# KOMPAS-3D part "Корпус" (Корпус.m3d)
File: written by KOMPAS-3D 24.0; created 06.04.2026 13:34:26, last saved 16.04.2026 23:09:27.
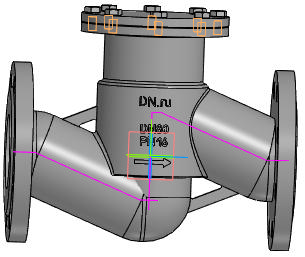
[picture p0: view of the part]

Document properties: Автор: R2D2; Полное имя файла: E:\Работа\Зайцев\VSO3131M-F-S Клапан запорный DN.ru Ду15-100 Ру16\DN80\исходные материалы\Корпус.m3d

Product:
- Body: Труба / Нестандартная труба / L = 159.4 мм  | qty 1
    Материал: Нестандартная труба (density 7856 kg/m3)
    Масса: 35.070684
    Раздел спецификации: Детали
    Примечание: 7,96 кг
    additional columns: Pipeline; 0.09; 0; 0; 0.002; 0.1594; true; 0.04
- Body: Труба / Нестандартная труба / L = 204.9 мм  | qty 1
    Материал: Нестандартная труба (density 7856 kg/m3)
    Масса: 35.070684
    Раздел спецификации: Детали
    Примечание: 10,24 кг
    additional columns: Pipeline; 0.09; 0; 0; 0.002; 0.20491; true; 0.04
- Body: Тело 4  | qty 1
    Материал: Нестандартная труба (density 7856 kg/m3)
    Масса: 35.070684
- Body: Тело 5  | qty 1
    Материал: Нестандартная труба (density 7856 kg/m3)
    Масса: 35.070684
- Body: Тело 8  | qty 1
    Материал: Нестандартная труба (density 7856 kg/m3)
    Масса: 35.070684
- Body: Тело 9  | qty 1
    Материал: Нестандартная труба (density 7856 kg/m3)
    Масса: 35.070684
- Component [standard]: Hexagon head screw ISO 4017 - М10 x 20  | qty 8  | Масса: 0.023019; Рассекать на разрезах: no; source file: C:\Program Files\ASCON\KOMPAS-3D v24\Libs\PolynomLib\DATA\vault\Methods\Kompas\3D\PLib_Bolt_1_ISO_1100.m3d
- Part/product: Корпус
    Масса: 6.9

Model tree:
1. Труба
2. Труба:1  (labels: {F703FF30-5BE6-4673-A7F1-8EDA1BE1E2D1}; SHAPEOBJECT3D_ATTR_BUTT; SHAPEOBJECT3D_ATTR_VALID; SHAPEOBJECT3D_ATTR_BUTT_AREA)
     PIPE_R = 7
3. Труба:2  (labels: {F703FF30-5BE6-4673-A7F1-8EDA1BE1E2D1}; SHAPEOBJECT3D_ATTR_BUTT; SHAPEOBJECT3D_ATTR_VALID; SHAPEOBJECT3D_ATTR_BUTT_AREA)
     PIPE_R = 5
4. Колонна
5. Элемент выдавливания:1
     Смещение 1 = -1; Смещение 2 = -5
6. Скругление:17  (with: Ребро.Элемент выдавливания:1)
     Радиус = 1
7. Скругление:18  (with: Ребро.Элемент выдавливания:1)
8. Скругление:24  (with: Ребро.Скругление:18, Ребро.Элемент выдавливания:1)
     Радиус = 1
9. Элемент выдавливания:2
     Расстояние 1 = 6
10. Скругление:19  (with: Ребро.Элемент выдавливания:2)
     Радиус = 2
11. Эскиз:4  (with: Грань.Элемент выдавливания:1)
12. Элемент выдавливания:3
     Расстояние 1 = 53.5
13. Скругление:21  (with: Ребро.Элемент выдавливания:3)
14. ОТЛИВКА
15. Скругление:6  (with: Грань.Элемент выдавливания:1)
     Радиус = 2
16. Элемент выдавливания:6  (with: Грань.Элемент выдавливания:1)
     Смещение 1 = 4
17. ЛЕЙБЛ
18. Элемент выдавливания:7  (with: Грань.Элемент выдавливания:1)
     Расстояние 1 = 60.9814; Смещение 1 = 1
19. Фланец верх  (with: Ребро.Элемент выдавливания:3)
20. Элемент вращения:2
     Угол 1 = 360
21. Эскиз:12  (with: Грань.Элемент вращения:2)
22. Элемент выдавливания:9  (with: Грань.Элемент вращения:2)
     Расстояние 2 = 20
23. Массив по концентрической сетке:1  (with: Элемент выдавливания:9, Эскиз:12, Грань.Элемент вращения:2)  (8 pattern instances)
     Шаг 2 = 360
24. Фланец
25. Элемент вращения:1
     Угол 1 = 360
26. отвертие во фланце  (with: Грань.Элемент вращения:1)
27. Элемент выдавливания:8
28. Массив по концентрической сетке:2  (with: Элемент выдавливания:8, Эскиз:10, Грань.Элемент вращения:1)  (8 pattern instances)
     Шаг 2 = 360
29. Зеркальный массив:1
30. Экземпляр ( 1 )
31. Экземпляр ( 2 )  (with: Элемент вращения:1, Массив по концентрической сетке:2, Экземпляр ( 1 ), Элемент выдавливания:8)
32. Экземпляр ( 3 )  (with: Элемент выдавливания:8)
33. Экземпляр ( 4 )  (with: Элемент выдавливания:8)
34. Экземпляр ( 5 )  (with: Элемент выдавливания:8)
35. Экземпляр ( 6 )  (with: Элемент выдавливания:8)
36. Экземпляр ( 7 )  (with: Элемент выдавливания:8)
37. Экземпляр ( 8 )  (with: Элемент выдавливания:8)
38. Скругление:25  (with: Ребро.Элемент вращения:2)
     Радиус = 2
39. Скругление:26  (with: Массив по концентрической сетке:1, Грань.Элемент вращения:2)  (labels: Грань.Элемент выдавливания:9.Экземпляр ( 1, 3 ))  (8 pattern instances)
     Радиус = 2; N 1 = 1; Шаг 1 = 10; Шаг 2 = 360; Номер 1 = 1

Expressions: DS/2+3; D1/2; DN/2; DS-v977*4; LL/2; D1-v1234*2; D/2+56-20
Referenced files in C:\Program Files\ASCON\KOMPAS-3D v24\Libs\Pipeline\: StylesTemplate.a3d, TemplateHPH, InsulationStylesTemplate.a3d, Insulation
Referenced files in C:\Program Files\ASCON\KOMPAS-3D v24\Templates\: Констр. чертеж А3 гориз. перв. лист.cdt
Referenced files in E:\Работа\Зайцев\VSO3131M-F-S Клапан запорный DN.ru Ду15-100 Ру40\DN20\исходные материалы\: 
Referenced files in C:\Program Files\ASCON\KOMPAS-3D v24\Libs\PolynomLib\DATA\vault\Methods\Kompas\3D\: PLib_Bolt_1_ISO_1100.m3d
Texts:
  Отводы ГОСТ 17375-2001
  Констр. чертеж А3 гориз. перв. лист.cdt
  BOSimple***PART:c031cb5e-65ec-2f83-1ced-75228c8ad34f***PART:A259_7B16EF33AB1642D2[16;1,5;20;10;-;Undefined]
  GOST 26.020 Pr3
  var3D
  смещение колонны вниз
  LL-10
  DN+10
  Hexagon head screw ISO 4017 - М10 x 20 (1)
  hole1
  hole2
  Труба / Нестандартная труба / L = %s мм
